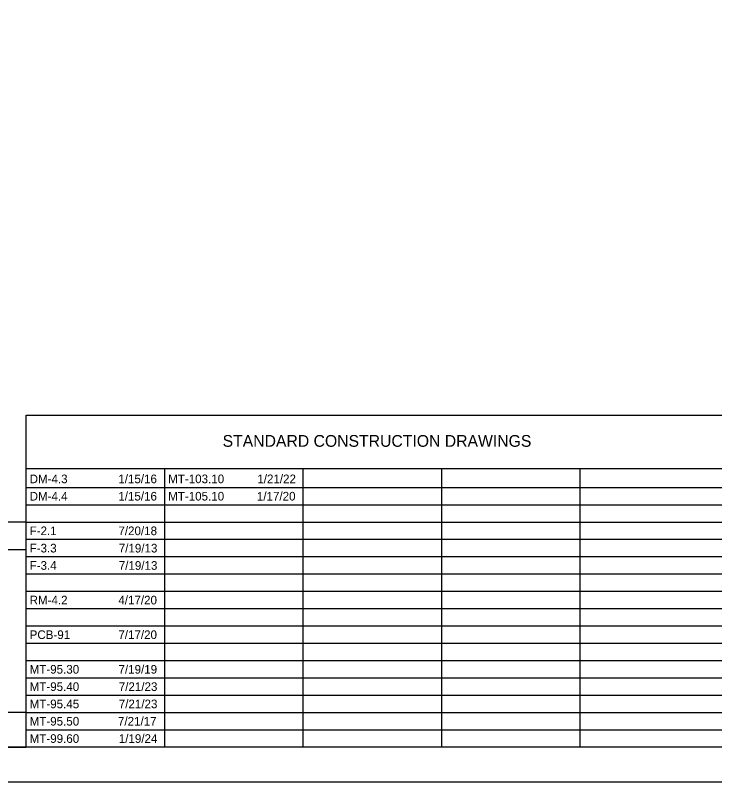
# Model space of a CAD drawing. Extents: x 0 to 34, y 0 to 22.
# Drawn here: x 9.99 to 20.09, y 0 to 11.07 of the extents above; entities that cross this region are included whole.
import ezdxf

# ---------------------------------------------------------------- set-up
doc = ezdxf.new("R2010")
doc.units = 0
for name, color, linetype in [('Default', 7, 'Continuous'), ('SH_Border', 7, 'Continuous'), ('SH_Cut_Line', 7, 'Continuous'), ('SH_Data', 7, 'Continuous'), ('SH_Text', 7, 'Continuous')]:
    doc.layers.add(name, color=color, linetype=linetype)

msp = doc.modelspace()

# ---------------------------------------------------------------- linework, layer by layer
at = {"layer": 'SH_Border'}
msp.add_lwpolyline([(1.5, 21.5), (33.5, 21.5), (33.5, 0.5), (1.5, 0.5)], close=True, dxfattribs=at)
at = {"layer": 'SH_Cut_Line'}
msp.add_lwpolyline([(0, 0), (34, 0), (34, 22), (0, 22)], close=True, dxfattribs=at)
at = {"layer": 'SH_Data'}
for p, q in [((10.15, 5.292), (23.6, 5.292)), ((10.15, 0.5), (10.15, 5.292)), ((10.15, 4.521), (23.6, 4.521)), ((12.15, 0.5), (12.15, 4.521)), ((14.15, 0.5), (14.15, 4.521)), ((16.15, 0.5), (16.15, 4.521)), ((18.15, 0.5), (18.15, 4.521)), ((10.15, 4.25), (23.6, 4.25)), ((10.15, 4), (23.6, 4)), ((10.15, 3.75), (7.35, 3.75)), ((10.15, 3.75), (23.6, 3.75)), ((10.15, 0.5), (10.15, 3.75)), ((10.15, 3.5), (23.6, 3.5)), ((10.15, 3.35), (7.35, 3.35)), ((10.15, 3.25), (23.6, 3.25)), ((10.15, 3), (23.6, 3)), ((10.15, 2.75), (23.6, 2.75)), ((10.15, 2.5), (23.6, 2.5)), ((10.15, 2.25), (23.6, 2.25)), ((10.15, 2), (23.6, 2)), ((10.15, 1.75), (23.6, 1.75)), ((10.15, 1.5), (23.6, 1.5)), ((10.15, 1.25), (23.6, 1.25)), ((10.15, 1), (23.6, 1)), ((10.15, 0.75), (23.6, 0.75)), ((10.15, 0.5), (7.35, 0.5))]:
    msp.add_line(p, q, dxfattribs=at)
msp.add_lwpolyline([(10.15, 0.5), (10.15, 1), (7.35, 1), (7.35, 0.5)], close=True, dxfattribs=at)

# ---------------------------------------------------------------- texts
at = {"layer": 'Default'}
for s, p in [('DM-4.3', (10.2, 4.31)), ('1/15/16', (11.48, 4.31)), ('MT-103.10', (12.2, 4.31)), ('1/21/22', (13.487, 4.31)), ('DM-4.4', (10.2, 4.06)), ('1/15/16', (11.48, 4.06)), ('MT-105.10', (12.2, 4.06)), ('1/17/20', (13.481, 4.06)), ('F-2.1', (10.2, 3.56)), ('7/20/18', (11.482, 3.56)), ('F-3.3', (10.2, 3.31)), ('7/19/13', (11.487, 3.31)), ('F-3.4', (10.2, 3.06)), ('7/19/13', (11.487, 3.06)), ('RM-4.2', (10.2, 2.56)), ('4/17/20', (11.481, 2.56)), ('PCB-91', (10.2, 2.06)), ('7/17/20', (11.481, 2.06)), ('MT-95.30', (10.2, 1.56)), ('7/19/19', (11.483, 1.56)), ('7/21/23', (11.487, 1.31)), ('MT-95.40', (10.2, 1.31)), ('MT-95.45', (10.2, 1.06)), ('7/21/23', (11.487, 1.06)), ('MT-95.50', (10.2, 0.81)), ('7/21/17', (11.475, 0.81)), ('MT-99.60', (10.2, 0.56)), ('1/19/24', (11.487, 0.56))]:
    msp.add_text(s, height=0.125, dxfattribs=at).set_placement(p)
at = {"layer": 'SH_Text'}
msp.add_text('STANDARD CONSTRUCTION DRAWINGS', height=0.17, dxfattribs=at).set_placement((12.986, 4.836))

doc.saveas('drawing.dxf')
